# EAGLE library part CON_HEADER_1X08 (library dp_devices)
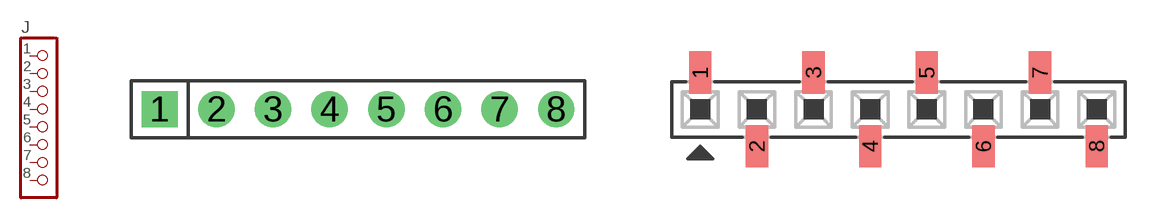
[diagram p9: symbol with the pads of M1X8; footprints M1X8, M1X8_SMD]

Designator prefix J

## CON_HEADER_1X08-PTH  [M1X8]
1  1  pas
2  2  pas
3  3  pas
4  4  pas
5  5  pas
6  6  pas
7  7  pas
8  8  pas

## CON_HEADER_1X08-SMD  [M1X8_SMD]
Pads as for M1X8

## Footprint M1X8 (pad centres in mm)
drill 1.02 pad 1.632 square: 1 -8.89,0
drill 1.02 pad 1.632 round: 2 -6.35,0; 3 -3.81,0; 4 -1.27,0; 5 1.27,0; 6 3.81,0; 7 6.35,0; 8 8.89,0

## Footprint M1X8_SMD (pad centres in mm)
1x08 0.1" header SMD, 1.00 x 1.90 pad size Mfr no: NPTC081KFXC-RC NPTC081KFXC-RC
smd 1 x 1.9: 1 -8.89,1.65; 2 -6.35,-1.65; 3 -3.81,1.65; 4 -1.27,-1.65; 5 1.27,1.65; 6 3.81,-1.65; 7 6.35,1.65; 8 8.89,-1.65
